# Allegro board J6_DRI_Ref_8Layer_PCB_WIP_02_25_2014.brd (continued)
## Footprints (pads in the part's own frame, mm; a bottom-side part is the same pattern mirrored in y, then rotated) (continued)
PBS32-12X57
  rect 0.305x1.448 smd: 1(-1.75,-3.277) 2(-1.25,-3.277) 3(-0.749,-3.277) 4(-0.249,-3.277) 5(0.249,-3.277) 6(0.749,-3.277) 7(1.25,-3.277) 8(1.75,-3.277) 17(1.75,3.277) 18(1.25,3.277) 19(0.749,3.277) 20(0.249,3.277) 21(-0.249,3.277) 22(-0.749,3.277) 23(-1.25,3.277) 24(-1.75,3.277)
  rect 1.448x0.305 smd: 9(3.277,-1.75) 10(3.277,-1.25) 11(3.277,-0.749) 12(3.277,-0.249) 13(3.277,0.249) 14(3.277,0.749) 15(3.277,1.25) 16(3.277,1.75) 25(-3.277,1.75) 26(-3.277,1.25) 27(-3.277,0.749) 28(-3.277,0.249) 29(-3.277,-0.249) 30(-3.277,-0.749) 31(-3.277,-1.25) 32(-3.277,-1.75)
POWERMITE-CASE457-04
  rect 2.667x2.54 smd: 1(0,0)
  rect 0.762x1.27 smd: 2(2.349,0)
PW20-14X70
  oval 0.356x1.778 smd: 1(-2.926,-2.987) 2(-2.276,-2.987) 3(-1.626,-2.987) 4(-0.975,-2.987) 5(-0.325,-2.987) 6(0.325,-2.987) 7(0.975,-2.987) 8(1.626,-2.987) 9(2.276,-2.987) 10(2.926,-2.987) 11(2.926,2.987) 12(2.276,2.987) 13(1.626,2.987) 14(0.975,2.987) 15(0.325,2.987) 16(-0.325,2.987) 17(-0.975,2.987) 18(-1.626,2.987) 19(-2.276,2.987) 20(-2.926,2.987)
PWR-Q5A-SLPS319
  rect 0.711x1.397 smd: 1(-1.905,0) 2(-0.635,0) 3(0.635,0) 4(1.905,0)
  custom 1.111x1.111 smd: 5(0,2.781)
QFN48-11X35
  rect 0.279x0.864 smd: 1(-2.748,-3.454) 2(-2.25,-3.454) 3(-1.75,-3.454) 4(-1.25,-3.454) 5(-0.749,-3.454) 6(-0.249,-3.454) 7(0.249,-3.454) 8(0.749,-3.454) 9(1.25,-3.454) 10(1.75,-3.454) 11(2.25,-3.454) 12(2.748,-3.454) 25(2.748,3.454) 26(2.25,3.454) 27(1.75,3.454) 28(1.25,3.454) 29(0.749,3.454) 30(0.249,3.454) 31(-0.249,3.454) 32(-0.749,3.454) 33(-1.25,3.454) 34(-1.75,3.454) 35(-2.25,3.454) 36(-2.748,3.454)
  rect 0.864x0.279 smd: 13(3.454,-2.748) 14(3.454,-2.25) 15(3.454,-1.75) 16(3.454,-1.25) 17(3.454,-0.749) 18(3.454,-0.249) 19(3.454,0.249) 20(3.454,0.749) 21(3.454,1.25) 22(3.454,1.75) 23(3.454,2.25) 24(3.454,2.748) 37(-3.454,2.748) 38(-3.454,2.25) 39(-3.454,1.75) 40(-3.454,1.25) 41(-3.454,0.749) 42(-3.454,0.249) 43(-3.454,-0.249) 44(-3.454,-0.749) 45(-3.454,-1.25) 46(-3.454,-1.75) 47(-3.454,-2.25) 48(-3.454,-2.748)
  rect 5.334x5.334 smd: 49(0,0)
QSE_020
  round 0.508 hole 1.041 unplated: (-10.058,-2.667) (10.058,-2.667)
  rect 0.406x2.286 smd: 1(7.569,2.87) 2(7.569,-2.87) 3(6.782,2.87) 4(6.782,-2.87) 5(5.969,2.87) 6(5.969,-2.87) 7(5.182,2.87) 8(5.182,-2.87) 9(4.369,2.87) 10(4.369,-2.87) 11(3.581,2.87) 12(3.581,-2.87) 13(2.769,2.87) 14(2.769,-2.87) 15(1.981,2.87) 16(1.981,-2.87) 17(1.168,2.87) 18(1.168,-2.87) 19(0.381,2.87) 20(0.381,-2.87) 21(-0.406,2.87) 22(-0.406,-2.87) 23(-1.219,2.87) 24(-1.219,-2.87) 25(-2.007,2.87) 26(-2.007,-2.87) 27(-2.819,2.87) 28(-2.819,-2.87) 29(-3.607,2.87) 30(-3.607,-2.87) 31(-4.42,2.87) 32(-4.42,-2.87) 33(-5.207,2.87) 34(-5.207,-2.87) 35(-6.02,2.87) 36(-6.02,-2.87) 37(-6.807,2.87) 38(-6.807,-2.87) 39(-7.595,2.87) 40(-7.595,-2.87)
  rect 2.794x0.432 smd: 41(-8.052,0) 44(8.052,0)
  rect 4.699x0.432 smd: 42(-3.175,0) 43(3.175,0)
QSH-030-01-F
  round 0.508 hole 1.016 unplated: (-10.061,2.667) (10.061,2.667)
  rect 0.279x2.273 smd: 1(-7.249,-2.865) 2(-7.249,2.865) 3(-6.749,-2.865) 4(-6.749,2.865) 5(-6.248,-2.865) 6(-6.248,2.865) 7(-5.748,-2.865) 8(-5.748,2.865) 9(-5.248,-2.865) 10(-5.248,2.865) 11(-4.75,-2.865) 12(-4.75,2.865) 13(-4.249,-2.865) 14(-4.249,2.865) 15(-3.749,-2.865) 16(-3.749,2.865) 17(-3.249,-2.865) 18(-3.249,2.865) 19(-2.748,-2.865) 20(-2.748,2.865) 21(-2.25,-2.865) 22(-2.25,2.865) 23(-1.75,-2.865) 24(-1.75,2.865) 25(-1.25,-2.865) 26(-1.25,2.865) 27(-0.749,-2.865) 28(-0.749,2.865) 29(-0.249,-2.865) 30(-0.249,2.865) 31(0.249,-2.865) 32(0.249,2.865) 33(0.749,-2.865) 34(0.749,2.865) 35(1.25,-2.865) 36(1.25,2.865) 37(1.75,-2.865) 38(1.75,2.865) 39(2.25,-2.865) 40(2.25,2.865) 41(2.748,-2.865) 42(2.748,2.865) 43(3.249,-2.865) 44(3.249,2.865) 45(3.749,-2.865) 46(3.749,2.865) 47(4.249,-2.865) 48(4.249,2.865) 49(4.75,-2.865) 50(4.75,2.865) 51(5.248,-2.865) 52(5.248,2.865) 53(5.748,-2.865) 54(5.748,2.865) 55(6.248,-2.865) 56(6.248,2.865) 57(6.749,-2.865) 58(6.749,2.865) 59(7.249,-2.865) 60(7.249,2.865)
  rect 2.54x0.432 smd: 61(-8.065,0) 64(8.065,0)
  rect 4.699x0.432 smd: 62(-3.175,0) 63(3.175,0)
R201-6P6SPC
  rect 0.47x0.381 smd: 1(-0.343,0) 2(0.343,0)
R402-25
  round 0.635 smd: 1(-0.508,0) 2(0.508,0)
R603-35X45
  oval 0.889x1.143 smd: 1(-0.762,0) 2(0.762,0)
R1206-40X70
  oval 1.016x1.778 smd: 1(-1.524,0) 2(1.524,0)
R2512
  rect 1.651x3.175 smd: 1(-3.239,0) 2(3.239,0)
R2725-125X250
  rect 3.175x6.858 smd: 1(-2.248,0) 2(2.248,0)
RGY16-12X34
  oval 0.864x0.305 smd: 1(-2.032,-0.749) 8(2.032,-0.749) 9(2.032,0.749) 16(-2.032,0.749)
  oval 0.305x0.864 smd: 2(-1.252,-1.765) 3(-0.752,-1.765) 4(-0.252,-1.765) 5(0.249,-1.765) 6(0.749,-1.765) 7(1.25,-1.765) 10(1.25,1.765) 11(0.749,1.765) 12(0.249,1.765) 13(-0.252,1.765) 14(-0.752,1.765) 15(-1.252,1.765)
  rect 2.489x2.032 smd: 17(0,0)
RGZ48-11X34
  rect 0.279x0.864 smd: 1(-2.748,-3.531) 2(-2.25,-3.531) 3(-1.75,-3.531) 4(-1.25,-3.531) 5(-0.749,-3.531) 6(-0.249,-3.531) 7(0.249,-3.531) 8(0.749,-3.531) 9(1.25,-3.531) 10(1.75,-3.531) 11(2.25,-3.531) 12(2.748,-3.531) 25(2.748,3.531) 26(2.25,3.531) 27(1.75,3.531) 28(1.25,3.531) 29(0.749,3.531) 30(0.249,3.531) 31(-0.249,3.531) 32(-0.749,3.531) 33(-1.25,3.531) 34(-1.75,3.531) 35(-2.25,3.531) 36(-2.748,3.531)
  rect 0.864x0.279 smd: 13(3.531,-2.748) 14(3.531,-2.25) 15(3.531,-1.75) 16(3.531,-1.25) 17(3.531,-0.749) 18(3.531,-0.249) 19(3.531,0.249) 20(3.531,0.749) 21(3.531,1.25) 22(3.531,1.75) 23(3.531,2.25) 24(3.531,2.748) 37(-3.531,2.748) 38(-3.531,2.25) 39(-3.531,1.75) 40(-3.531,1.25) 41(-3.531,0.749) 42(-3.531,0.249) 43(-3.531,-0.249) 44(-3.531,-0.749) 45(-3.531,-1.25) 46(-3.531,-1.75) 47(-3.531,-2.25) 48(-3.531,-2.748)
  rect 5.334x5.334 smd: 49(0,0)
RHL24-PVQFN-TI
  rect 0.711x0.305 smd: 1(-2.819,-0.953) 12(2.819,-0.953) 13(2.819,0.953) 24(-2.819,0.953)
  rect 0.305x0.711 smd: 2(-2.25,-1.829) 3(-1.75,-1.829) 4(-1.25,-1.829) 5(-0.749,-1.829) 6(-0.249,-1.829) 7(0.249,-1.829) 8(0.749,-1.829) 9(1.25,-1.829) 10(1.75,-1.829) 11(2.25,-1.829) 14(2.25,1.829) 15(1.75,1.829) 16(1.25,1.829) 17(0.749,1.829) 18(0.249,1.829) 19(-0.249,1.829) 20(-0.749,1.829) 21(-1.25,1.829) 22(-1.75,1.829) 23(-2.25,1.829)
  custom 0.508x0.508 smd: 25(0,0)
RPAK8-10X25-28V
  rect 0.406x0.635 smd: 1(-0.823,-0.521) 4(0.823,-0.521) 5(0.823,0.521) 8(-0.823,0.521)
  rect 0.254x0.635 smd: 2(-0.249,-0.521) 3(0.249,-0.521) 6(0.249,0.521) 7(-0.249,0.521)
RTE16-12X34
  oval 0.305x0.864 smd: 1(-0.747,-1.524) 2(-0.249,-1.524) 3(0.249,-1.524) 4(0.747,-1.524) 9(0.747,1.524) 10(0.249,1.524) 11(-0.249,1.524) 12(-0.747,1.524)
  oval 0.864x0.305 smd: 5(1.524,-0.747) 6(1.524,-0.249) 7(1.524,0.249) 8(1.524,0.747) 13(-1.524,0.747) 14(-1.524,0.249) 15(-1.524,-0.249) 16(-1.524,-0.747)
  rect 1.524x1.524 smd: 17(0,0)
SD12-202X60
  custom 0.559x0.559 smd: 1(-2.972,0) 2(2.972,0)
SO8-25X75
  oval 0.635x1.905 smd: 1(-1.905,-2.794) 2(-0.635,-2.794) 3(0.635,-2.794) 4(1.905,-2.794) 5(1.905,2.794) 6(0.635,2.794) 7(-0.635,2.794) 8(-1.905,2.794)
SO8-25X75-295
  oval 0.635x2.54 smd: 1(-1.905,-3.086) 2(-0.635,-3.086) 3(0.635,-3.086) 4(1.905,-3.086) 5(1.905,3.086) 6(0.635,3.086) 7(-0.635,3.086) 8(-1.905,3.086)
SO16-25X75-300
  oval 0.635x1.905 smd: 1(-4.445,-4.699) 2(-3.175,-4.699) 3(-1.905,-4.699) 4(-0.635,-4.699) 5(0.635,-4.699) 6(1.905,-4.699) 7(3.175,-4.699) 8(4.445,-4.699) 9(4.445,4.699) 10(3.175,4.699) 11(1.905,4.699) 12(0.635,4.699) 13(-0.635,4.699) 14(-1.905,4.699) 15(-3.175,4.699) 16(-4.445,4.699)
ST_3500
  round 0.508 hole 1.6 unplated: (0,3.797) (0,-3.188)
  rect 2.54x2.388 smd: 1(-3.683,4.915) 2(-3.48,-4.407) 3(3.683,3.01)
  rect 2.921x2.489 smd: 4(0.762,-8.42)
SW4-7914G
  rect 1.27x1.778 smd: 1(1.27,2.769) 2(1.27,-2.769) 3(-1.27,2.769) 4(-1.27,-2.769)
TO-252-D-PAK
  rect 1.397x3.048 smd: 1(-2.311,-6.413) 3(2.311,-6.413)
  rect 6.35x7.62 smd: 4(0,0.102)
TP1-18RD8
  round 0.457 hole 0.203: 1(0,0)
TP20
  round 0.762 smd: 1(0,0)
unnamed
  round 1.27 smd: 1(0,0)
XTAL2-75X94
  rect 1.905x2.413 smd: 1(-2.235,0) 2(2.235,0)
XTAL2-CM519-DUAL-CTS407
  rect 1.295x2.21 smd: 1(-2.1,0) 2(2.1,0)
  rect 1.397x2.21 smd: 3(-1.27,3.2) 4(-1.27,-3.2) 5(1.27,-3.2) 6(1.27,3.2)
XTAL4-23X47-SSP-T7
  rect 1.194x0.584 smd: 1(-3.15,-0.445) 2(3.15,-0.445) 3(3.15,0.445) 4(-3.15,0.445)
XTAL4-55X87
  rect 2.21x1.397 smd: 1(-2.896,-1.25) 2(2.896,-1.25) 3(2.896,1.25) 4(-2.896,1.25)
ZWS169-13P8
  round 0.35 smd: A1(4.8,-4.8) A2(4,-4.8) A3(3.2,-4.8) A4(2.4,-4.8) A5(1.6,-4.8) A6(0.8,-4.8) A7(0,-4.8) A8(-0.8,-4.8) A9(-1.6,-4.8) A10(-2.4,-4.8) A11(-3.2,-4.8) A12(-4,-4.8) A13(-4.8,-4.8) B1(4.8,-4) B2(4,-4) B3(3.2,-4) B4(2.4,-4) B5(1.6,-4) B6(0.8,-4) B7(0,-4) B8(-0.8,-4) B9(-1.6,-4) B10(-2.4,-4) B11(-3.2,-4) B12(-4,-4) B13(-4.8,-4) C1(4.8,-3.2) C2(4,-3.2) C3(3.2,-3.2) C4(2.4,-3.2) C5(1.6,-3.2) C6(0.8,-3.2) C7(0,-3.2) C8(-0.8,-3.2) C9(-1.6,-3.2) C10(-2.4,-3.2) C11(-3.2,-3.2) C12(-4,-3.2) C13(-4.8,-3.2) D1(4.8,-2.4) D2(4,-2.4) D3(3.2,-2.4) D4(2.4,-2.4) D5(1.6,-2.4) D6(0.8,-2.4) D7(0,-2.4) D8(-0.8,-2.4) D9(-1.6,-2.4) D10(-2.4,-2.4) D11(-3.2,-2.4) D12(-4,-2.4) D13(-4.8,-2.4) E1(4.8,-1.6) E2(4,-1.6) E3(3.2,-1.6) E4(2.4,-1.6) E5(1.6,-1.6) E6(0.8,-1.6) E7(0,-1.6) E8(-0.8,-1.6) E9(-1.6,-1.6) E10(-2.4,-1.6) E11(-3.2,-1.6) E12(-4,-1.6) E13(-4.8,-1.6) F1(4.8,-0.8) F2(4,-0.8) F3(3.2,-0.8) F4(2.4,-0.8) F5(1.6,-0.8) F6(0.8,-0.8) F7(0,-0.8) F8(-0.8,-0.8) F9(-1.6,-0.8) F10(-2.4,-0.8) F11(-3.2,-0.8) F12(-4,-0.8) F13(-4.8,-0.8) G1(4.8,0) G2(4,0) G3(3.2,0) G4(2.4,0) G5(1.6,0) G6(0.8,0) G7(0,0) G8(-0.8,0) G9(-1.6,0) G10(-2.4,0) G11(-3.2,0) G12(-4,0) G13(-4.8,0) H1(4.8,0.8) H2(4,0.8) H3(3.2,0.8) H4(2.4,0.8) H5(1.6,0.8) H6(0.8,0.8) H7(0,0.8) H8(-0.8,0.8) H9(-1.6,0.8) H10(-2.4,0.8) H11(-3.2,0.8) H12(-4,0.8) H13(-4.8,0.8) J1(4.8,1.6) J2(4,1.6) J3(3.2,1.6) J4(2.4,1.6) J5(1.6,1.6) J6(0.8,1.6) J7(0,1.6) J8(-0.8,1.6) J9(-1.6,1.6) J10(-2.4,1.6) J11(-3.2,1.6) J12(-4,1.6) J13(-4.8,1.6) K1(4.8,2.4) K2(4,2.4) K3(3.2,2.4) K4(2.4,2.4) K5(1.6,2.4) K6(0.8,2.4) K7(0,2.4) K8(-0.8,2.4) K9(-1.6,2.4) K10(-2.4,2.4) K11(-3.2,2.4) K12(-4,2.4) K13(-4.8,2.4) L1(4.8,3.2) L2(4,3.2) L3(3.2,3.2) L4(2.4,3.2) L5(1.6,3.2) L6(0.8,3.2) L7(0,3.2) L8(-0.8,3.2) L9(-1.6,3.2) L10(-2.4,3.2) L11(-3.2,3.2) L12(-4,3.2) L13(-4.8,3.2) M1(4.8,4) M2(4,4) M3(3.2,4) M4(2.4,4) M5(1.6,4) M6(0.8,4) M7(0,4) M8(-0.8,4) M9(-1.6,4) M10(-2.4,4) M11(-3.2,4) M12(-4,4) M13(-4.8,4) N1(4.8,4.8) N2(4,4.8) N3(3.2,4.8) N4(2.4,4.8) N5(1.6,4.8) N6(0.8,4.8) N7(0,4.8) N8(-0.8,4.8) N9(-1.6,4.8) N10(-2.4,4.8) N11(-3.2,4.8) N12(-4,4.8) N13(-4.8,4.8)

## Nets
1V8_I2C1_SCL: P9.31 R597.2 R708.1 U45.L1(I2C1_SCL_SCK) U50.3(SCL1)
1V8_I2C1_SDA: P9.33 R593.2 R709.1 U45.L2(I2C1_SDA_SDI) U50.4(SDA1)
GND: C7.2 C8.2 C13.2 C14.2 C15.2 C16.2 C45.2 C47.2 C49.2 C50.2 C51.2 C52.2 C60.1 C61.1 C62.1 C63.1 C67.2 C71.2 C72.2 C74.2 C76.1 C77.2 C78.1 C79.2 C80.2 C86.2 C87.2 C89.2 C90.1 C91.1 C92.1 C93.1 C94.1 C95.1 C96.1 C99.1 C100.1 C101.2 C102.1 C103.1 C104.2 C105.1 C106.2 C107.2 C108.1 C109.2 C110.2 C111.1 C112.2 C113.2 C115.2 C116.2 C117.2 C118.2 C119.2 C130.2 C131.2 C132.2 C133.2 C134.2 C136.2 C137.2 C138.2 C139.2 C140.2 C141.2 C142.2 C143.2 C144.2 C147.2 C148.2 C151.2 C152.2 C153.2 C154.2 C155.2 C156.2 C157.1 C158.2 C159.2 C160.2 C161.2 C162.2 C163.2 C169.2 C170.2 C171.2 C172.2 C174.1 C177.2 C178.2 C179.1 C182.2 C183.2 C184.2 C185.2 C186.1 C187.1 C188.1 C189.2 C190.2 C191.1 C192.1 C193.2 C194.2 C195.2 C196.2 C199.2 C200.2 C201.1 C202.1 C210.2 C211.2 C212.2 C213.2 C214.2 C228.2 C229.2 C231.2 C232.2 C233.2 C234.2 C235.2 C236.2 C269.2 C273.2 C274.2 C280.2 C290.2 C293.2 C295.1 C304.1 C305.2 C306.2 C309.1 C314.2 C318.2 C319.2 C325.2 C326.1 C327.1 C328.1 C329.2 C330.2 C331.2 C332.2 C335.2 C338.1 C340.2 C341.1 C342.1 C344.2 C345.2 C346.1 C348.2 C349.1 C350.1 C351.2 C352.2 C353.1 C354.1 C355.2 C356.2 C357.2 C358.2 C359.1 C360.1 C363.1 C364.1 C365.2 C366.2 C367.1 C368.1 C369.2 C370.1 C371.2 C372.2 C373.1 C374.1 C375.1 C376.1 C377.1 C378.1 C379.1 C380.1 C381.1 C382.2 C384.2 C385.2 C386.1 C387.2 C388.1 C389.2 C390.1 C391.1 C392.1 C393.1 C394.1 C395.1 C396.2 C399.1 C400.1 C401.2 C402.2 C403.1 C404.2 C405.2 C406.2 C407.1 C408.1 C409.1 C410.1 C411.2 C412.1 C413.2 C414.1 C415.1 C416.2 C417.2 C418.2 C419.2 C420.2 C421.2 C422.2 C423.2 C424.2 C425.2 C426.2 C427.2 C429.2 C430.2 C431.2 C432.1 C433.2 C434.1 C435.2 C436.2 C437.1 C438.2 C439.2 C440.2 C441.2 C442.2 C443.2 C444.1 C445.2 C446.2 C447.2 C448.2 C449.2 C450.1 C451.2 C453.1 C454.2 C455.1 C456.1 C457.2 C458.1 C459.1 C460.2 C461.1 C462.2 C463.2 C464.2 C465.1 C466.2 C467.2 C468.2 C469.2 C470.2 C471.2 C472.2 C473.2 C474.2 C475.2 C477.2 C478.1 C479.2 C480.2 C481.2 C482.2 C483.1 C484.2 C485.2 C486.2 C487.1 C489.2 C490.2 C491.2 C492.2 C493.2 C494.2 C495.2 C496.2 C497.2 C498.1 C500.2 C501.2 C502.2 C503.2 C504.2 C506.2 C507.1 C508.2 C509.2 C510.2 C511.2 C512.2 C513.1 C514.2 C516.2 C517.2 C518.1 C519.2 C520.2 C521.2 C522.2 C523.1 C524.2 C525.2 C526.2 C527.2 C528.2 C529.2 C530.2 C531.2 C532.2 C535.2 C536.2 C537.2 C538.2 C539.2 C540.2 C541.2 C542.1 C545.2 C546.2 C548.2 C549.2 C550.2 C553.2 C556.2 C557.2 C559.2 C560.2 C561.2 C562.2 C563.2 C564.2 C565.2 C566.2 C567.2 C568.2 C569.2 C570.2 C571.2 C572.2 C573.2 C574.2 C575.2 C576.2 C577.2 C578.2 C579.1 C580.2 C581.2 C582.2 C583.2 C584.2 C585.2 C586.2 C587.2 C588.2 C589.2 C590.2 C591.2 C592.2 C593.2 C594.2 C595.2 C596.2 C597.2 C598.2 C600.2 C602.2 C603.2 C605.2 C606.2 C607.1 C608.2 C609.2 C610.2 C611.2 C612.2 C613.2 C614.2 C615.2 C616.2 C617.2 C618.2 C619.2 C621.2 C622.2 C623.2 C624.2 C625.2 C628.2 C629.2 C630.2 C631.2 C632.2 C633.2 C636.2 C637.2 C638.2 C639.2 C640.2 C641.2 C644.2 C645.2 C649.2 C650.2 C655.2 C656.2 C657.2 C658.1 C659.1 C664.2 C665.2 C666.2 C667.2 C668.2 C669.2 C670.2 C671.2 C672.2 C673.2 C674.2 C675.2 C676.2 C677.2 C678.2 C679.2 C680.2 C683.2 C693.2 C696.2 C708.2 C715.2 C716.2 C717.2 C718.2 C719.2 C720.2 C721.2 C733.1 C734.1 C735.2 C785.2 C786.2 C787.2 C789.1 C790.1 C792.2 C793.2 C794.2 C795.2 C796.2 C797.1 C798.2 C799.2 C800.1 C801.1 C810.1 E1.2 E2.2 E3.2 E4.2 E5.2 E6.2 E8.2 E9.2 E10.2 E11.2 J17.16(GND16) J17.57(GND57) J17.58(GND58) J17.61(GNDCT1) J17.62(GNDCT2) J17.63(GNDCT3) J17.64(GNDCT4) P1.17 P1.18 P1.41(G1) P1.42(G2) P1.43(G3) P1.44(G4) P5.9 P5.10 P9.2 P9.3 P9.6 P9.9 P9.18 P9.19 P9.22 P9.37 P9.42 P9.47 P9.60 P9.63 P9.64 P9.77 P9.83 P9.87 P9.92 P9.95 P9.97 P12.1(SHIELD) P14.6(VSS) Q3.1(S1) Q3.2(S2) Q3.3(S3) Q4.1(S1) Q4.2(S2) Q4.3(S3) R9.2 R10.2 R11.2 R83.1 R84.1 R85.1 R110.2 R111.2 R112.2 R116.2 R117.2 R118.2 R119.2 R120.2 R121.2 R122.2 R123.2 R124.2 R125.2 R145.1 R152.2 R154.2 R157.2 R178.2 R179.2 R191.2 R196.2 R200.2 R205.2 R206.2 R241.2 R245.2 R256.1 R257.2 R260.2 R262.2 R266.2 R273.1 R276.1 R277.1 R278.1 R287.2 R288.2 R289.2 R291.1 R333.2 R338.2 R455.1 R461.1 R463.1 R464.1 R472.1 R473.2 R481.1 R483.2 R513.2 R515.2 R518.2 R529.2 R532.1 R535.2 R537.2 R555.1 R565.2 R569.1 R570.2 R574.2 R576.2 R578.2 R588.2 R589.2 R590.2 R591.2 R592.2 R599.1 R615.2 R617.2 R620.2 R625.2 R636.2 R642.2 R643.2 R644.2 R675.2 R691.2 R692.2 R693.2 R694.2 R695.2 R702.2 R714.1 R715.2 R760.1 R762.1 R832.2 R838.2 R848.2 R849.2 R911.2 R915.2 R943.1 R946.1 R953.1 R954.1 R955.2 R958.2 R?.2 SW4.1(A) SW4.2(AA) U3.15(RES0) U3.18(RES1(RES2)) U3.49(DAP(PWRPAD)) U6.3(GND) U8.4(TAB) U18.10(VSS) U23.9(PGNDA) U23.19(AGND.1) U23.23(AGND.2) U23.30(PGNDB) U23.39(PWR PAD) U35.2(DIR) U35.11(GND#11) U35.12(GND#12) U35.13(GND#13) U35.25(PP) U36.1(GND) U37.2(GND) U41.7(2A2) U41.8(GND.1) U41.9(GND.2) U41.17(GND.3) U43.1(GND) U44.2(GND) U45.A1(SUB_GND_A1) U45.A4(REFGND1) U45.A7(GNDANA) U45.A13(SUB_GND_A13) U45.B2(GPADC_IN0) U45.B10(SUB_GND_B10) U45.B11(SUB_GND_B11) U45.C2(GPADC_IN1) U45.C3(GPADC_IN2) U45.C12(SMPS12_FBK_GND) U45.D4(SMPS7_GND_1) U45.D5(SMPS7_GND_2) U45.D6(SUB_GND_D6) U45.D7(SUB_GND_D7) U45.D10(SMPS1_GND_1) U45.E4(SMPS7_GND_3) U45.E7(VAC/ACOK) U45.E8(SUB_GND_E8) U45.E9(SMPS1_GND_2) U45.E10(SMPS1_GND_3) U45.F4(SMPS4_GND_1) U45.F5(AGND.1) U45.F6(SUB_GND_F6) U45.F7(SUB_GND_F7) U45.F9(SMPS2_GND_1) U45.F10(SMPS2_GND_2) U45.G4(SMPS4_GND_2) U45.G5(SMPS4_GND_3) U45.G7(SUB_GND_G7) U45.G10(SMPS2_GND_3) U45.H4(SMPS5_GND_1) U45.H5(SMPS5_GND_2) U45.H6(SUB_GND_H6) U45.H7(SUB_GND_H7) U45.H10(SMPS3_GND_1) U45.J4(SMPS5_GND_3) U45.J6(SUB_GND_J6) U45.J9(SMPS3_GND_2) U45.J10(SMPS3_GND_3) U45.K3(SMPS45_FDBK_GND) U45.L5(SMPS6_GND) U45.L6(SMPS6_GND_1) U45.L7(SMPS9_GND) U45.L8(SMPS9_GND_1) U45.L9(SMPS8_GND_1) U45.L10(SMPS8_GND) U45.M1(SUB_GND_M1) U45.M2(SUB_GND_M2) U45.M12(GND_DIG) U45.M13(AGND.2) U45.N1(SUB_GND_N1) U45.N2(VIO_GND) U45.N13(SUB_GND_N13) U46.11(GND#11) U46.12(GND#12) U46.13(GND#13) U46.25(PP) U48.7(2A2) U48.8(GND.1) U48.9(GND.2) U48.17(GND.3) U50.1(GND) U52.A1(VSS.9) U52.A2(VSS.11) U52.A6(VSS.15) U52.A14(VSS.41) U52.A23(VSS.68) U52.A28(VSS.79) U52.AA8(VSS.17) U52.AA9(VSS.19) U52.AA10(VSS.14) U52.AA11(VSSA_USB.2) U52.AA14(VSS.48) U52.AA15(VSS.51) U52.AA20(VSS.61) U52.AB11(VSSA_USB.1) U52.AB14(VSS.40) U52.AB20(VSS.60) U52.AD1(VSS.3) U52.AD10(VSSA_USB3) U52.AD13(VSSA_PCIE.1) U52.AD19(VSSA_HDMI.2) U52.AD24(VSS.70) U52.AE10(VSSA_SATA) U52.AE13(VSSA_PCIE.2) U52.AE19(VSSA_HDMI.1) U52.AG1(VSS.2) U52.AH1(VSS.1) U52.AH2(VSS.10) U52.AH8(VSS.53) U52.AH20(VSS.52) U52.AH28(VSS.75) U52.B1(VSS.8) U52.D13(VSS.39) U52.D19(VSS.59) U52.E13(VSS.38) U52.E19(VSS.58) U52.F1(VSS.7) U52.F7(VSS.54) U52.G7(VSS.57) U52.G8(VSS.65) U52.G9(VSS.66) U52.H12(VSS.33) U52.J12(VSS.32) U52.J15(VSS.XX) U52.J28(VSS.78) U52.K1(VSS.6) U52.K4(VSS.12) U52.K5(VSS.13) U52.K15(VSS.28) U52.K24(VSS.55) U52.K25(VSS.56) U52.L13(VSS.37) U52.L14(VSS.46) U52.M19(VSS.69) U52.N14(VSS.X5) U52.N15(VSS.16) U52.N19(VSS.18) U52.N24(VSS.72) U52.N25(VSS.74) U52.P28(VSS.77) U52.R1(VSS.5) U52.R12(VSS.29) U52.R13(VSS.X6) U52.R15(VSS.43) U52.R21(VSS.64) U52.T10(VSS.21) U52.T11(VSS.26) U52.T12(VSS.23) U52.T14(VSS.X7) U52.T15(VSS.42) U52.T17(VSS.47) U52.T18(VSS.24) U52.T21(VSS.27) U52.U14(VSSA_VIDEO) U52.U15(VSS.X8) U52.U17(VSS.X9) U52.U20(VSS.62) U52.U21(VSS.63) U52.V15(VSS.30) U52.V17(VSS.X10) U52.W1(VSS.4) U52.W15(VSS.36) U52.W24(VSS.71) U52.W25(VSS.73) U52.W28(VSS.76) U54.2(GND) U55.2(GND) U55.3(ENN) U56.6(GND) U56.11(PP1) U59.15(AVSS_ADC) U59.20(DRVSS.1) U59.21(DRVSS.2) U59.26(AVSS_DAC) U59.42(DVSS) U59.49(TPAD) U62.3(GND) U63.3(GND.1) U63.4(GND.2) U63.5(AGND) U63.17(PWRPAD) U64.4(PGND) U64.8(GND) U64.11(PWRPAD) U65.A9(VSS.1) U65.B1(VSSQ.1) U65.B3(VSS.2) U65.B9(VSSQ.2) U65.D1(VSSQ.3) U65.D8(VSSQ.4) U65.E1(VSS.3) U65.E2(VSSQ.5) U65.E8(VSSQ.6) U65.F9(VSSQ.7) U65.G1(VSSQ.8) U65.G8(VSS.4) U65.G9(VSSQ.9) U65.J2(VSSDL) U65.J8(VSS.5) U65.M1(VSS.6) U65.M9(VSS.7) U65.P1(VSS.8) U65.P9(VSS.9) U65.T1(VSS.10) U65.T9(VSS.11) U66.A9(VSS.1) U66.B1(VSSQ.1) U66.B3(VSS.2) U66.B9(VSSQ.2) U66.D1(VSSQ.3) U66.D8(VSSQ.4) U66.E1(VSS.3) U66.E2(VSSQ.5) U66.E8(VSSQ.6) U66.F9(VSSQ.7) U66.G1(VSSQ.8) U66.G8(VSS.4) U66.G9(VSSQ.9) U66.J2(VSSDL) U66.J8(VSS.5) U66.M1(VSS.6) U66.M9(VSS.7) U66.P1(VSS.8) U66.P9(VSS.9) U66.T1(VSS.10) U66.T9(VSS.11) U67.A1(VSS.1) U67.A8(VSS.2) U67.B1(VSS.3) U67.B2(VSSQ#B2) U67.B8(VSSQ#B8) U67.C9(VSSQ#C9) U67.D1(VSSQ#D1) U67.D8(VSS.4) U67.D9(VSSQ#D9) U67.F2(VSS.5) U67.F8(VSS.6) U67.J1(VSS.7) U67.J9(VSS.8) U67.L1(VSS.9) U67.L9(VSS.10) U67.N1(VSS.11) U67.N9(VSS.12) U68.A1(VSS.1) U68.A8(VSS.2) U68.B1(VSS.3) U68.B2(VSSQ#B2) U68.B8(VSSQ#B8) U68.C9(VSSQ#C9) U68.D1(VSSQ#D1) U68.D8(VSS.4) U68.D9(VSSQ#D9) U68.F2(VSS.5) U68.F8(VSS.6) U68.J1(VSS.7) U68.J9(VSS.8) U68.L1(VSS.9) U68.L9(VSS.10) U68.N1(VSS.11) U68.N9(VSS.12) U69.A1(VSS.1) U69.A8(VSS.2) U69.B1(VSS.3) U69.B2(VSSQ#B2) U69.B8(VSSQ#B8) U69.C9(VSSQ#C9) U69.D1(VSSQ#D1) U69.D8(VSS.4) U69.D9(VSSQ#D9) U69.F2(VSS.5) U69.F8(VSS.6) U69.J1(VSS.7) U69.J9(VSS.8) U69.L1(VSS.9) U69.L9(VSS.10) U69.N1(VSS.11) U69.N9(VSS.12) U72.8(GND) U72.11(PWR_PAD) U73.8(GND) U73.11(PWR_PAD) U77.4(GND) U78.4(GND) U79.4(GND) U92.5(GND) U92.9(PWR_PAD) U100.11(GND1) U100.17(B3) U100.18(B2) U100.20(B1) U101.4(GND) U101.5(DIR) U102.2(GND) U104.2(GND) U104.5(DIR) U105.4(VSS) U110.3(GND) U115.A1(VSS.1) U115.A8(VSS.2) U115.B1(VSS.3) U115.B2(VSSQ#B2) U115.B8(VSSQ#B8) U115.C9(VSSQ#C9) U115.D1(VSSQ#D1) U115.D8(VSS.4) U115.D9(VSSQ#D9) U115.F2(VSS.5) U115.F8(VSS.6) U115.J1(VSS.7) U115.J9(VSS.8) U115.L1(VSS.9) U115.L9(VSS.10) U115.N1(VSS.11) U115.N9(VSS.12) U116.A1(VSS.1) U116.A8(VSS.2) U116.B1(VSS.3) U116.B2(VSSQ#B2) U116.B8(VSSQ#B8) U116.C9(VSSQ#C9) U116.D1(VSSQ#D1) U116.D8(VSS.4) U116.D9(VSSQ#D9) U116.F2(VSS.5) U116.F8(VSS.6) U116.J1(VSS.7) U116.J9(VSS.8) U116.L1(VSS.9) U116.L9(VSS.10) U116.N1(VSS.11) U116.N9(VSS.12) U117.2(GND) U121.C4(VSS.1) U121.E7(VSS.2) U121.G5(VSS.3) U121.H10(VSS.4) U121.K8(VSS.5) U121.N2(VSS.6) U121.N7(VSS.7) U121.P4(VSS.8) U121.P6(VSS.9) U122.5(GND) U123.2(GND) U129.3(GND) U130.3(GND) U131.4(GND) U132.3(PLL_AGND) U132.7(AGND) U132.19(DGND) U132.31(CH_AGND) Y3.2 Y3.3
VBATT_12V: F1.2 R453.2
VBUS_USB1: C80.1 L8.1 U73.9(VBUS.2) U73.10(VBUS.1)
VBUS_USB1_SW: C79.1 L8.2 R154.1 U36.6(OUT3) U36.7(OUT2) U36.8(OUT1)
VBUS_USB2: C87.1 L12.1 U72.9(VBUS.2) U72.10(VBUS.1)
VBUS_USB2_SW: C86.1 L12.2 R179.1 U43.6(OUT3) U43.7(OUT2) U43.8(OUT1)
VCC_SENSE: R549.2 U45.B3(VCC_SENSE)
VDD_???: U45.B1(SMPS7_FDBK) U45.L11(SMPS8_FDBK)
VDD_CORE: C326.2 C363.2 C364.2 C386.2 C388.2 C390.2 C393.2 C394.2 C395.2 C456.2 C487.2 C498.2 L11.1 U45.K6(SMPS6_FBK) U52.H13(VDD.18) U52.H14(VDD.22) U52.J17(VDD.X1) U52.J18(VDD.X2) U52.L7(VDD.34) U52.L8(VDD.15) U52.N10(VDD.6) U52.N13(VDD.16) U52.P11(VDD.9) U52.P12(VDD.12) U52.P13(VDD.X3) U52.R11(VDD.8) U52.R16(VDD.26) U52.R19(VDD.27) U52.T13(VDD.13) U52.T16(VDD.25) U52.T19(VDD.X7) U52.U8(VDD.29) U52.U9(VDD.2) U52.U13(VDD.3) U52.U16(VDD.X8) U52.V8(VDD.1) U52.V16(VDD.X9)
VDD_DCDC_DDR_1V35: C154.1 L20.2 R279.2
VDD_DDR: C136.1 C137.1 C138.1 C139.1 C140.1 C143.1 C148.1 C158.1 C159.1 C160.1 C161.1 C162.1 C163.1 C164.2 C165.2 C166.2 C167.2 C169.1 C170.1 C171.1 C172.1 C175.2 C176.2 C180.2 C181.2 C182.1 C183.1 C184.1 C185.1 C187.2 C189.1 C190.1 C191.2 C193.1 C194.1 C195.1 C196.1 C197.2 C198.2 C199.1 C200.1 C201.2 C203.2 C204.2 C205.2 C206.2 C207.2 C208.2 C209.2 C210.1 C211.1 C212.1 C213.1 C214.1 C350.2 C508.1 C528.1 C537.1 C541.1 C548.1 C549.1 C556.1 C557.1 C559.1 C560.1 C561.1 C562.1 C563.1 C564.1 C569.1 C570.1 C571.1 C572.1 C574.1 C576.1 C577.1 C578.1 C580.1 C581.1 C582.1 C583.1 C584.1 C585.1 C586.1 C587.1 C588.1 C589.1 C590.1 C591.1 C592.1 C593.1 C594.1 C595.1 C596.1 C597.1 C598.1 C599.2 C600.1 C601.2 C602.1 C603.1 C605.1 C606.1 C608.1 C609.1 C610.1 C611.1 C612.1 C613.1 C614.1 C615.1 C616.1 C621.1 C622.1 C623.1 C624.1 C625.1 C626.2 C627.2 C630.1 C631.1 C632.1 C633.1 C634.2 C635.2 C636.1 C637.1 C638.1 C639.1 C640.1 C641.1 C642.2 C643.2 C644.1 C645.1 C649.1 C650.1 C651.2 C652.2 C653.2 C654.2 C655.1 C656.1 C657.1 C659.2 C660.2 C661.2 C662.2 C663.2 C664.1 C665.1 C666.1 C667.1 C668.1 C669.1 C670.1 C671.1 C672.1 C673.1 C674.1 C675.1 C676.1 C677.1 C678.1 C679.1 L13.1 R292.2 U45.K13(SMPS3_FDBK) U52.AA21(VDDS_DDR1.4) U52.AA22(VDDS_DDR1.2) U52.AB21(VDDS_DDR1.3) U52.AB22(VDDS_DDR1.7) U52.AB24(VDDS_DDR1.10) U52.AB25(VDDS_DDR1.11) U52.AC22(VDDS_DDR1.6) U52.AD26(VDDS_DDR1.12) U52.AG20(VDDS_DDR1.9) U52.AG28(VDDS_DDR1.5) U52.AH27(VDDS_DDR1.13) U52.E24(VDDS_DDR2.9) U52.G22(VDDS_DDR2.5) U52.G23(VDDS_DDR2.6) U52.H20(VDDS_DDR2.1) U52.H21(VDDS_DDR2.11) U52.H22(VDDS_DDR2.4) U52.J27(VDDS_DDR2.12) U52.L20(VDDS_DDR2.8) U52.L21(VDDS_DDR2.3) U52.M20(VDDS_DDR2.13) U52.M21(VDDS_DDR2.2) U52.T24(VDDS_DDR2.7) U52.T25(VDDS_DDR2.10) U52.W16(VDDS_DDR1.1) U52.W27(VDDS_DDR1.8) U64.2(VLDOIN) U65.A1(VDDQ.1) U65.A8(VDDQ.2) U65.B2(VDD.1) U65.C1(VDDQ.3) U65.C9(VDDQ.4) U65.D2(VDDQ.5) U65.D9(VDD.2) U65.E9(VDDQ.6) U65.F1(VDDQ.7) U65.G7(VDD.3) U65.H2(VDDQ.8) U65.H9(VDDQ.9) U65.K2(VDDL) U65.K8(VDD.4) U65.N1(VDD.5) U65.N9(VDD.6) U65.R1(VDD.7) U65.R9(VDD.8) U66.A1(VDDQ.1) U66.A8(VDDQ.2) U66.B2(VDD.1) U66.C1(VDDQ.3) U66.C9(VDDQ.4) U66.D2(VDDQ.5) U66.D9(VDD.2) U66.E9(VDDQ.6) U66.F1(VDDQ.7) U66.G7(VDD.3) U66.H2(VDDQ.8) U66.H9(VDDQ.9) U66.K2(VDDL) U66.K8(VDD.4) U66.N1(VDD.5) U66.N9(VDD.6) U66.R1(VDD.7) U66.R9(VDD.8) U67.A2(VDD.1) U67.A9(VDD.2) U67.B9(VDDQ.1) U67.C1(VDDQ.2) U67.D7(VDD.3) U67.E2(VDDQ.3) U67.E9(VDDQ.4) U67.G2(VDD.4) U67.G8(VDD.5) U67.K1(VDD.6) U67.K9(VDD.7) U67.M1(VDD.8) U67.M9(VDD.9) U68.A2(VDD.1) U68.A9(VDD.2) U68.B9(VDDQ.1) U68.C1(VDDQ.2) U68.D7(VDD.3) U68.E2(VDDQ.3) U68.E9(VDDQ.4) U68.G2(VDD.4) U68.G8(VDD.5) U68.K1(VDD.6) U68.K9(VDD.7) U68.M1(VDD.8) U68.M9(VDD.9) U69.A2(VDD.1) U69.A9(VDD.2) U69.B9(VDDQ.1) U69.C1(VDDQ.2) U69.D7(VDD.3) U69.E2(VDDQ.3) U69.E9(VDDQ.4) U69.G2(VDD.4) U69.G8(VDD.5) U69.K1(VDD.6) U69.K9(VDD.7) U69.M1(VDD.8) U69.M9(VDD.9) U115.A2(VDD.1) U115.A9(VDD.2) U115.B9(VDDQ.1) U115.C1(VDDQ.2) U115.D7(VDD.3) U115.E2(VDDQ.3) U115.E9(VDDQ.4) U115.G2(VDD.4) U115.G8(VDD.5) U115.K1(VDD.6) U115.K9(VDD.7) U115.M1(VDD.8) U115.M9(VDD.9) U116.A2(VDD.1) U116.A9(VDD.2) U116.B9(VDDQ.1) U116.C1(VDDQ.2) U116.D7(VDD.3) U116.E2(VDDQ.3) U116.E9(VDDQ.4) U116.G2(VDD.4) U116.G8(VDD.5) U116.K1(VDD.6) U116.K9(VDD.7) U116.M1(VDD.8) U116.M9(VDD.9)
VDD_DSPEVE_IVA_GPU: C89.1 C90.2 C105.2 C107.1 C108.2 C109.1 C111.2 C112.1 C118.1 C119.1 C349.2 C372.1 C373.2 C374.2 C377.2 C453.2 C460.1 C463.1 C465.2 C466.1 C469.1 C473.1 C474.1 C475.1 C478.2 C483.2 C492.1 C495.1 L14.1 L16.1 U45.K2(SMPS45_FDBK) U52.J13(VDD_DSPEVE.7) U52.K10(VDD_DSPEVE.8) U52.K11(VDD_DSPEVE.9) U52.K12(VDD_DSPEVE.10) U52.K13(VDD_DSPEVE.11) U52.L10(VDD_DSPEVE.2) U52.L11(VDD_DSPEVE.4) U52.L12(VDD_DSPEVE.12) U52.M10(VDD_DSPEVE.1) U52.M11(VDD_DSPEVE.5) U52.M12(VDD_DSPEVE.3) U52.M13(VDD_DSPEVE.6) U52.U11(VDD_GPU.5) U52.U12(VDD_GPU.6) U52.U18(VDD_IVA.1) U52.U19(VDD_IVA.2) U52.V10(VDD_GPU.2) U52.V11(VDD_GPU.3) U52.V14(VDD_GPU.7) U52.V18(VDD_IVA.3) U52.V19(VDD_IVA.4) U52.W10(VDD_GPU.1) U52.W11(VDD_GPU.4) U52.W13(VDD_GPU.8)
VDD_MPU: C91.2 C92.2 C93.2 C94.2 C95.2 C96.2 C356.1 C359.2 C360.2 C365.1 C366.1 C367.2 C368.2 C369.1 C370.2 C378.2 C384.1 C385.1 C387.1 C389.1 C391.2 C392.2 C396.1 C410.2 L15.1 L17.1 R554.1 U45.B13(SMPS12_FBK) U52.K17(VDD_MPU.10) U52.K18(VDD_MPU.2) U52.L15(VDD_MPU.11) U52.L16(VDD_MPU.12) U52.L17(VDD_MPU.6) U52.L18(VDD_MPU.8) U52.L19(VDD_MPU.3) U52.M15(VDD_MPU.13) U52.M16(VDD_MPU.14) U52.M17(VDD_MPU.5) U52.M18(VDD_MPU.7) U52.N17(VDD_MPU.4) U52.N18(VDD_MPU.1) U52.P17(VDD_MPU.15) U52.P18(VDD_MPU.9) U52.R18(VDD_MPU.16)
VDD_RTC: C102.2 C117.1 R531.1 U45.A5(LDO9_OUT) U52.AB15(VDD_RTC)
VDDA_ANA: C680.1 U45.C8(LDOVANA_OUT)
VDDA_DEBUG_1V8: C414.2 C420.1 C427.1 C490.1 E4.1 U52.N11(VDDA_DEBUG) U52.N12(VDDA_DSP_EVE)
VDDA_HDMI: C538.1 C539.1 E9.1 U52.Y17(VDDA_HDMI)
VDDA_IVA_1V8: C415.2 C422.1 C429.1 C497.1 E3.1 U52.R14(VDDA_GPU) U52.R17(VDDA_IVA)
VDDA_MPU_1V8: C413.1 C419.1 C426.1 C507.2 E5.1 U52.M14(VDDA_ABE_PER) U52.N16(VDDA_MPU)
VDDA_PCI_1P8: C417.1 C424.1 E1.1 U52.AA16(VDDA_PCIE1) U52.AA17(VDDA_PCIE0) U52.W14(VDDA_PCIE)
VDDA_PHY_1V8: C352.1 C486.1 C510.1 C511.1 E1.3 E2.3 E9.3 U45.K11(LDO3_OUT) U52.AA13(VDDA_USB1) U52.AB12(VDDA_USB2) U52.W12(VDDA_USB3)
VDDA_PLL_1V8: C103.2 C521.1 C522.1 E3.3 E4.3 E5.3 E6.3 U45.B5(LDOLN_OUT) U52.AD16(VDDA_OSC.1) U52.AE16(VDDA_OSC.2)
VDDA_RTC: C110.1 C431.1 U45.A8(LDOVRTC_OUT) U52.AB13(VDDA_RTC)
VDDA_SATA_1P8: C416.1 C423.1 E2.1 U52.V13(VDDA_SATA)
VDDA_VIDEO_1V8: C412.2 C418.1 C425.1 C491.1 E6.1 U52.P14(VDDA_VIDEO) U52.P15(VDDA_GMAC_CORE) U52.P16(VDDA_DDR)
VDDR_VREFSTL: C147.1 C177.1 C178.1 C197.1 C198.1 C203.1 C204.1 C205.1 C514.1 C607.2 C617.1 C618.1 C619.1 C628.1 C629.1 C651.1 C652.1 U52.N22(DDR2_VREF0) U52.Y18(DDR1_VREF0) U64.6(REFOUT) U65.H1(VREFDQ) U65.M8(VREFCA) U66.H1(VREFDQ) U66.M8(VREFCA) U67.E1(VREFDQ) U67.J8(VREFCA) U68.E1(VREFDQ) U68.J8(VREFCA) U69.E1(VREFDQ) U69.J8(VREFCA) U115.E1(VREFDQ) U115.J8(VREFCA) U116.E1(VREFDQ) U116.J8(VREFCA)
VDDS_1V8: C327.2 C357.1 C371.1 C382.1 C399.2 C400.2 C401.1 C402.1 C406.1 C461.2 C470.1 C471.1 C518.2 C524.1 C530.1 E10.3 L10.1 R192.1 U45.J8(SMPS9_FBK) U52.AA7(VDDS_MLBP.1) U52.AA18(VDDS18V_DDR1.1) U52.AA19(VDDS18V_DDR1.2) U52.G18(VDDS18V.8) U52.H17(VDDS18V.11) U52.J21(VDDS18V_DDR2.3) U52.J22(VDDS18V_DDR2.4) U52.M8(VDDS18V.9) U52.M9(VDDS18V.7) U52.N8(VDDS18V.4) U52.N21(VDDS18V_DDR2.2) U52.P8(VDDS18V.5) U52.P20(VDDS18V_DDR2.5) U52.P21(VDDS18V_DDR2.1) U52.R8(VDDS18V.3) U52.T8(VDDS18V.2) U52.V21(VDDS18V.12) U52.V22(VDDS18V.6) U52.W17(VDDS18V.10) U52.W18(VDDS18V.1) U52.W21(VDDS18V_DDR1.4) U52.Y7(VDDS_MLBP.2) U52.Y21(VDDS18V_DDR1.3)
VDDSHV: C104.1 C355.1 C436.1 C437.2 C438.1 C442.1 C443.1 C444.2 C445.1 C449.1 C450.2 C454.1 C455.2 C457.1 C458.2 C464.1 C482.1 C484.1 C493.1 C494.1 C496.1 C500.1 C502.1 C526.1 C542.2 C545.1 E11.3 U52.AB6(VDDSHV7.1) U52.AB7(VDDSHV7.2) U52.AD5(VDDSHV6.2) U52.AD7(VDDSHV6.4) U52.AE7(VDDSHV6.3) U52.AF5(VDDSHV6.1) U52.B6(VDDSHV2.1) U52.B23(VDDSHV3.9) U52.C24(VDDSHV4.1) U52.D10(VDDSHV2.5) U52.D16(VDDSHV3.4) U52.D22(VDDSHV3.8) U52.E3(VDDSHV1.1) U52.E5(VDDSHV1.4) U52.E10(VDDSHV2.4) U52.E16(VDDSHV3.3) U52.E22(VDDSHV3.7) U52.G4(VDDSHV1.2) U52.G5(VDDSHV1.3) U52.G15(VDDSHV3.2) U52.H8(VDDSHV1.5) U52.H9(VDDSHV1.6) U52.H10(VDDSHV2.2) U52.H11(VDDSHV2.3) U52.H15(VDDSHV3.1) U52.H16(VDDSHV3.6) U52.H18(VDDSHV3.5) U52.H19(VDDSHV3.10) U52.J8(VDDSHV11.2) U52.K8(VDDSHV11.1) U52.N4(VDDSHV10.2) U52.N5(VDDSHV10.4) U52.P10(VDDSHV10.6) U52.R7(VDDSHV10.5) U52.R10(VDDSHV10.7) U52.T4(VDDSHV10.1) U52.T5(VDDSHV10.3) U52.U10(VDDSHV9.3) U52.W4(VDDSHV9.1) U52.W5(VDDSHV9.2)
VDDSHV5: C101.1 C485.1 C527.1 C540.1 R204.1 R530.1 R605.2 U45.B6(LDO2_OUT) U52.V12(VDDSHV5) U54.5(VIO/NC) U110.5(VCC)
VDDSHV8: C430.1 C467.1 U45.C6(LDO1_OUT) U52.W8(VDDSHV8.2) U52.Y8(VDDSHV8.1)
VIN1A_CLK0: R957.1
VIN1A_D0: RN32.4(R4A)
VIN1A_D1: RN32.3(R3A)
VIN1A_D2: RN32.2(R2A)
VIN1A_D3: RN32.1(R1A)
VIN1A_D4: RN33.4(R4A)
VIN1A_D5: RN33.3(R3A)
VIN1A_D6: RN33.2(R2A)
VIN1A_D7: RN33.1(R1A)
VIN1A_DE0: R947.1
VIN1A_FLD0: R950.1
VIN1A_HSYNC0: R948.1
VIN1A_VSYNC0: R949.1
AIC_BCLK: R253.2 R642.1 U59.38(BCLK)
AIC_DIN: R251.2 R643.1 U59.40(DIN)
AIC_DOUT: R250.2 U59.41(DOUT)
AIC_MCA3_ACLKX: R253.1
AIC_MCA3_AFSX: R252.1
AIC_MCA3_AXR0: R251.1
AIC_MCA3_AXR1: R250.1
AIC_MCLK: R254.1
AIC_WCLK: R252.2 U59.39(WCLK)
BT_EN: P9.89 U46.20(B2)
BT_UART_CTS: P9.70 U46.15(B7)
BT_UART_RTS: P9.72 U35.16(B6)
BT_UART_RX: P9.68 U46.14(B8)
BT_UART_TX: P9.66 U35.17(B5)
COMQ_MMC0_CLK: P9.20 U104.3(A)
COMQ_MMC0_CMD: P9.24 R559.2 U100.5(A4)
COMQ_MMC0_DAT0: P9.26 R560.2 U100.6(A5)
COMQ_MMC0_DAT1: P9.28 R561.2 U100.7(A6)
COMQ_MMC0_DAT2: P9.30 R562.2 U100.8(A7)
COMQ_MMC0_DAT3: P9.32 R558.2 U100.9(A8)
CON_MMC1_CLK: P14.5(CLK) R17.2 R343.2 U78.3(IO1)
CON_MMC1_CMD: P14.3(CMD) R16.2 R344.2 U78.5(IO2)
CON_MMC1_DAT0: P14.7(DAT0) R18.2 R342.2 U77.5(IO2)
CON_MMC1_DAT1: P14.8(DAT1) R19.2 R341.2 U77.3(IO1)
CON_MMC1_DAT2: P14.1(DAT2) R14.2 R340.2 U79.5(IO2)
CON_MMC1_DAT3: P14.2(DAT3) R15.2 R345.2 U79.3(IO1)
CON_USB1_DM: FL1.3 U73.6(D-)
CON_USB1_DP: FL1.2 U73.7(D+)
CON_USB2_DM: FL4.3 U72.6(D-)
CON_USB2_DP: FL4.2 U72.7(D+)
CONN_ALT_TRST_N: J17.9(NTRST) R759.2
CONN_JTAG_TRST_N: J17.8(TRSTPD) R761.1
CPU_POR_RESETN: R596.1 U62.2(A) U102.1(R\E\S\E\T)
CPU_RESETN: R623.1
DBG_RX1: R106.1
DBG_TX1: U6.1(B) U6.2(A)
DCAN1_RX: U54.4(RXD)
DCAN1_TX: R617.1 U54.1(TXD)
ENET_GPIO5_15: P1.1
ENET_GPIO5_16: P1.2
ENET_GPIO5_17: P1.4
ENET_GPIO5_20: P1.10
ENET_GPIO5_21: P1.7
ENET_GPIO5_22: P1.3
ENET_GPIO5_23: P1.6
ENET_GPIO5_24: P1.5
ENET_GPIO5_25: P1.8
ENET_GPIO5_26: P1.16
ENET_GPIO5_27: P1.13
ENET_GPIO5_28: P1.9
ENET_GPIO5_29: P1.12
ENET_GPIO5_30: P1.11
ENET_GPIO5_31: P1.14
ENET_RST_INN: R914.1 R915.1 U130.1(B)
ENET_RSTN: P1.15 U130.4(Y)
EVM_12V: D1.2(A)
FM_I2S_CLK: P9.49 U48.13(1B1)
FM_I2S_DI: P9.53 U48.11(2B1)
FM_I2S_DO: P9.51 U35.18(B4)
FM_I2S_FSYNC: P9.55 U48.12(1B2)
FTDI_RX: P1.19 R100.2
FTDI_TX: P1.21 R911.1 U129.1(B) U129.2(A)
GA1: R451.2 U23.6(GA1)
GA2: R457.2 U23.8(GA2)
GB1: R450.2 U23.33(GB1)
GB2: R456.2 U23.31(GB2)
GP5[4]: U46.4(A2)
GP5[5]: U35.5(A3)
GP5[6]: U46.6(A4)
GP5[7]: U35.3(A1)
GP5[8]: U46.5(A3)
GPMC_D00: R80.2 R110.1
GPMC_D01: R81.2 R111.1
GPMC_D02: R82.2 R112.1
GPMC_D03: J21.1 R113.2
GPMC_D04: R84.2 R114.2
GPMC_D05: J24.1 R115.2
GPMC_D06: R86.2 R116.1
GPMC_D07: R87.2 R117.1
GPMC_D08: R88.2 R118.1
GPMC_D09: R89.2 R119.1
GPMC_D10: R90.2 R120.1
GPMC_D11: R91.2 R121.1
GPMC_D12: R92.2 R122.1
GPMC_D13: R93.2 R123.1
GPMC_D14: R94.2 R124.1
GPMC_D15: R95.2 R125.1
GPS_PPS_OUT: P9.50 U35.19(B3)
GPS_TIME_STAMP: P9.48 U46.18(B4)
H_DCAN1_RX: R232.2 U52.G19(DCAN1_RX/UART8_TXD/MMC2_SDWP/SA)
H_DCAN1_TX: U52.G20(DCAN1_TX/UART8_RXD/MMC2_SDCD/HD)
H_DDR1_A0: RN4.1(R1A) TP1MA19.1 TP1MB19.1 TP1MC14.1 U52.AD20(DDR1_A0) U65.N3(A0) U66.N3(A0) U67.K3(A0)
H_DDR1_A1: RN4.2(R2A) TP1MA20.1 TP1MB20.1 TP1MC16.1 U52.AC19(DDR1_A1) U65.P7(A1) U66.P7(A1) U67.L7(A1)
H_DDR1_A2: RN6.4(R4A) TP1MA27.1 TP1MB27.1 TP1MC26.1 U52.AC20(DDR1_A2) U65.P3(A2) U66.P3(A2) U67.L3(A2)
H_DDR1_A3: RN15.4(R4A) TP1MA14.1 TP1MB14.1 TP1MC13.1 U52.AB19(DDR1_A3) U65.N2(A3) U66.N2(A3) U67.K2(A3)
H_DDR1_A4: RN4.3(R3A) TP1MA16.1 TP1MB16.1 TP1MC17.1 U52.AF21(DDR1_A4) U65.P8(A4) U66.P8(A4) U67.L8(A4)
H_DDR1_A5: RN4.4(R4A) TP1MA21.1 TP1MB21.1 TP1MC18.1 U52.AH22(DDR1_A5) U65.P2(A5) U66.P2(A5) U67.L2(A5)
H_DDR1_A6: RN17.3(R3A) TP1MA22.1 TP1MB22.1 TP1MC21.1 U52.AG23(DDR1_A6) U65.R8(A6) U66.R8(A6) U67.M8(A6)
H_DDR1_A7: RN6.2(R2A) TP1MA17.1 TP1MB17.1 TP1MC22.1 U52.AE21(DDR1_A7) U65.R2(A7) U66.R2(A7) U67.M2(A7)
H_DDR1_A8: RN17.1(R1A) TP1MA26.1 TP1MB26.1 TP1MC25.1 U52.AF22(DDR1_A8) U65.T8(A8) U66.T8(A8) U67.N8(A8)
H_DDR1_A9: RN6.1(R1A) TP1MA25.1 TP1MB25.1 TP1MC19.1 U52.AE22(DDR1_A9) U65.R3(A9) U66.R3(A9) U67.M3(A9)
H_DDR1_A10: RN13.3(R3A) TP1MA8.1 TP1MB8.1 TP1MC6.1 U52.AD21(DDR1_A10) U65.L7(A10) U66.L7(A10) U67.H7(A10/AP)
H_DDR1_A11: RN17.4(R4A) TP1MA18.1 TP1MB18.1 TP1MC20.1 U52.AD22(DDR1_A11) U65.R7(A11) U66.R7(A11) U67.M7(A11)
H_DDR1_A12: RN15.1(R1A) TP1MA13.1 TP1MB13.1 TP1MC15.1 U52.AC21(DDR1_A12) U65.N7(A12) U66.N7(A12) U67.K7(A12/B\C\)
H_DDR1_A13: RN6.3(R3A) TP1MA23.1 TP1MB23.1 TP1MC23.1 U52.AF18(DDR1_A13) U65.T3(A13) U66.T3(A13) U67.N3(A13)
H_DDR1_A14: RN17.2(R2A) TP1MA24.1 TP1MB24.1 TP1MC24.1 U52.AE17(DDR1_A14) U65.T7(A14) U66.T7(A14) U67.N7(A14/NC)
H_DDR1_A15: RN13.1(R1A) TP1MA11.1 TP1MB11.1 TP1MC9.1 U52.AD18(DDR1_A15) U65.M7(NC.M7/A15) U66.M7(NC.M7/A15) U67.J7(A15/NC)
H_DDR1_BA0: RN2.4(R4A) TP1MA9.1 TP1MB9.1 TP1MC10.1 U52.AF17(DDR1_BA0) U65.M2(BA0) U66.M2(BA0) U67.J2(BA0)
H_DDR1_BA1: RN15.3(R3A) TP1MA12.1 TP1MB12.1 TP1MC12.1 U52.AE18(DDR1_BA1) U65.N8(BA1) U66.N8(BA1) U67.K8(BA1)
H_DDR1_BA2: RN15.2(R2A) TP1MA15.1 TP1MB15.1 TP1MC11.1 U52.AB18(DDR1_BA2) U65.M3(BA2) U66.M3(BA2) U67.J3(BA2)
H_DDR1_CASN: RN2.2(R2A) TP1MA3.1 TP1MB3.1 TP1MC5.1 U52.AC18(DDR1_CASN) U65.K3(CAS#) U66.K3(CAS#) U67.G3(C\A\S\)
H_DDR1_CKE: R689.1 TP1MA2.1 TP1MB2.1 TP1MC3.1 U52.AG22(DDR1_CKE) U65.K9(CKE) U66.K9(CKE) U67.G9(CKE)
H_DDR1_CLK0: R684.1 TP1MA1.1 TP1MB1.1 TP1MC2.1 U52.AG24(DDR1_CK) U65.J7(CK) U66.J7(CK) U67.F7(CK)
H_DDR1_CLK0N: R687.1 TP1MA4.1 TP1MB4.1 TP1MC4.1 U52.AH24(DDR1_NCK) U65.K7(CK#) U66.K7(CK#) U67.G7(C\K\)
H_DDR1_CSN0: RN2.3(R3A) TP1MA10.1 TP1MB10.1 TP1MC8.1 U52.AH23(DDR1_CS0N) U65.L2(CS#) U66.L2(CS#) U67.H2(C\S\)
H_DDR1_D0: U52.AF25(DDR1_D0) U65.H7(DQ7)
H_DDR1_D1: U52.AF26(DDR1_D1) U65.F8(DQ3)
H_DDR1_D2: U52.AG26(DDR1_D2) U65.F7(DQ1)
H_DDR1_D3: U52.AH26(DDR1_D3) U65.H8(DQ5)
H_DDR1_D4: U52.AF24(DDR1_D4) U65.E3(DQ0)
H_DDR1_D5: U52.AE24(DDR1_D5) U65.H3(DQ4)
H_DDR1_D6: U52.AF23(DDR1_D6) U65.F2(DQ2)
H_DDR1_D7: U52.AE23(DDR1_D7) U65.G2(DQ6)
H_DDR1_D8: U52.AC23(DDR1_D8) U65.A2(DQ13)
H_DDR1_D9: U52.AF27(DDR1_D9) U65.B8(DQ14)
H_DDR1_D10: U52.AG27(DDR1_D10) U65.A7(DQ12)
H_DDR1_D11: U52.AF28(DDR1_D11) U65.C8(DQ10)
H_DDR1_D12: U52.AE26(DDR1_D12) U65.C3(DQ9)
H_DDR1_D13: U52.AC25(DDR1_D13) U65.D7(DQ8)
H_DDR1_D14: U52.AC24(DDR1_D14) U65.A3(DQ15)
H_DDR1_D15: U52.AD25(DDR1_D15) U65.C2(DQ11)
H_DDR1_D16: U52.V20(DDR1_D16) U66.F8(DQ3)
H_DDR1_D17: U52.W20(DDR1_D17) U66.H8(DQ5)
H_DDR1_D18: U52.AB28(DDR1_D18) U66.F7(DQ1)
H_DDR1_D19: U52.AC28(DDR1_D19) U66.F2(DQ2)
H_DDR1_D20: U52.AC27(DDR1_D20) U66.E3(DQ0)
H_DDR1_D21: U52.Y19(DDR1_D21) U66.G2(DQ6)
H_DDR1_D22: U52.AB27(DDR1_D22) U66.H7(DQ7)
H_DDR1_D23: U52.Y20(DDR1_D23) U66.H3(DQ4)
H_DDR1_D24: U52.AA23(DDR1_D24) U66.C3(DQ9)
H_DDR1_D25: U52.Y22(DDR1_D25) U66.A7(DQ12)
H_DDR1_D26: U52.Y23(DDR1_D26) U66.B8(DQ14)
H_DDR1_D27: U52.AA24(DDR1_D27) U66.A3(DQ15)
H_DDR1_D28: U52.Y24(DDR1_D28) U66.C8(DQ10)
H_DDR1_D29: U52.AA26(DDR1_D29) U66.C2(DQ11)
H_DDR1_D30: U52.AA25(DDR1_D30) U66.A2(DQ13)
H_DDR1_D31: U52.AA28(DDR1_D31) U66.D7(DQ8)
H_DDR1_DQM0: U52.AD23(DDR1_DQM0) U65.E7(LDM)
H_DDR1_DQM1: U52.AB23(DDR1_DQM1) U65.D3(UDM)
H_DDR1_DQM2: U52.AC26(DDR1_DQM2) U66.E7(LDM)
H_DDR1_DQM3: U52.AA27(DDR1_DQM3) U66.D3(UDM)
H_DDR1_DQM_ECC: U52.V26(DDR1_DQM_ECC) U67.B7(DM/TDQS)
H_DDR1_DQS0: U52.AH25(DDR1_DQS0) U65.F3(LDQS)
H_DDR1_DQS1: U52.AE27(DDR1_DQS1) U65.C7(UDQS)
H_DDR1_DQS2: U52.AD27(DDR1_DQS2) U66.F3(LDQS)
H_DDR1_DQS3: U52.Y28(DDR1_DQS3) U66.C7(UDQS)
H_DDR1_DQS_ECC: U52.V27(DDR1_DQS_ECC) U67.C3(DQS)
H_DDR1_DQSN0: U52.AG25(DDR1_DQSN0) U65.G3(LDQS#)
H_DDR1_DQSN1: U52.AE28(DDR1_DQSN1) U65.B7(UDQS#)
H_DDR1_DQSN2: U52.AD28(DDR1_DQSN2) U66.G3(LDQS#)
H_DDR1_DQSN3: U52.Y27(DDR1_DQSN3) U66.B7(UDQS#)
H_DDR1_DQSN_ECC: U52.V28(DDR1_DQSN_ECC) U67.D3(D\Q\S\)
H_DDR1_ECC_D0: U52.W22(DDR1_ECC_D0) U67.E8(DQ5)
H_DDR1_ECC_D1: U52.V23(DDR1_ECC_D1) U67.C8(DQ3)
H_DDR1_ECC_D2: U52.W19(DDR1_ECC_D2) U67.E3(DQ4)
H_DDR1_ECC_D3: U52.W23(DDR1_ECC_D3) U67.D2(DQ6)
H_DDR1_ECC_D4: U52.Y25(DDR1_ECC_D4) U67.C7(DQ1)
H_DDR1_ECC_D5: U52.V24(DDR1_ECC_D5) U67.E7(DQ7)
H_DDR1_ECC_D6: U52.V25(DDR1_ECC_D6) U67.C2(DQ2)
H_DDR1_ECC_D7: U52.Y26(DDR1_ECC_D7) U67.B3(DQ0)
H_DDR1_ODT0: RN2.1(R1A) TP1MA5.1 TP1MB5.1 TP2MC1.1 U52.AE20(DDR1_ODT0) U65.K1(ODT) U66.K1(ODT) U67.G1(ODT)
H_DDR1_RASN: RN13.4(R4A) TP1MA6.1 TP1MB6.1 TP1MC1.1 U52.AF20(DDR1_RASN) U65.J3(RAS#) U66.J3(RAS#) U67.F3(R\A\S\)
H_DDR1_RST: U52.AG21(DDR1_RST) U65.T2(RSTN) U66.T2(RSTN) U67.N2(R\E\S\E\T\)
H_DDR1_WEN: RN13.2(R2A) TP1MA7.1 TP1MB7.1 TP1MC7.1 U52.AH21(DDR1_WEN) U65.L3(WE#) U66.L3(WE#) U67.H3(W\E\)
H_DDR2_A0: RN14.1(R1A) TP2MA15.1 TP2MB15.1 U52.R25(DDR2_A0) U68.K3(A0) U69.K3(A0) U115.K3(A0) U116.K3(A0)
H_DDR2_A1: RN16.4(R4A) TP2MA19.1 TP2MB19.1 U52.R26(DDR2_A1) U68.L7(A1) U69.L7(A1) U115.L7(A1) U116.L7(A1)
H_DDR2_A2: RN5.3(R3A) TP2MA20.1 TP2MB20.1 U52.R28(DDR2_A2) U68.L3(A2) U69.L3(A2) U115.L3(A2) U116.L3(A2)
H_DDR2_A3: RN5.1(R1A) TP2MA14.1 TP2MB14.1 U52.R27(DDR2_A3) U68.K2(A3) U69.K2(A3) U115.K2(A3) U116.K2(A3)
H_DDR2_A4: RN5.4(R4A) TP2MA17.1 TP2MB17.1 U52.P23(DDR2_A4) U68.L8(A4) U69.L8(A4) U115.L8(A4) U116.L8(A4)
H_DDR2_A5: RN5.2(R2A) TP2MA18.1 TP2MB18.1 U52.P22(DDR2_A5) U68.L2(A5) U69.L2(A5) U115.L2(A5) U116.L2(A5)
H_DDR2_A6: RN7.3(R3A) TP2MA24.1 TP2MB24.1 U52.P25(DDR2_A6) U68.M8(A6) U69.M8(A6) U115.M8(A6) U116.M8(A6)
H_DDR2_A7: RN16.3(R3A) TP2MA23.1 TP2MB23.1 U52.N20(DDR2_A7) U68.M2(A7) U69.M2(A7) U115.M2(A7) U116.M2(A7)
H_DDR2_A8: RN16.1(R1A) TP2MA27.1 TP2MB27.1 U52.P27(DDR2_A8) U68.N8(A8) U69.N8(A8) U115.N8(A8) U116.N8(A8)
H_DDR2_A9: RN7.1(R1A) TP2MA21.1 TP2MB21.1 U52.N27(DDR2_A9) U68.M3(A9) U69.M3(A9) U115.M3(A9) U116.M3(A9)
H_DDR2_A10: RN3.1(R1A) TP2MA7.1 TP2MB7.1 U52.N23(DDR2_A10) U68.H7(A10/AP) U69.H7(A10/AP) U115.H7(A10/AP) U116.H7(A10/AP)
H_DDR2_A11: RN7.2(R2A) TP2MA22.1 TP2MB22.1 U52.P26(DDR2_A11) U68.M7(A11) U69.M7(A11) U115.M7(A11) U116.M7(A11)
H_DDR2_A12: RN14.3(R3A) TP2MA16.1 TP2MB16.1 U52.N28(DDR2_A12) U68.K7(A12/B\C\) U69.K7(A12/B\C\) U115.K7(A12/B\C\) U116.K7(A12/B\C\)
H_DDR2_A13: RN16.2(R2A) TP2MA26.1 TP2MB26.1 U52.T22(DDR2_A13) U68.N3(A13) U69.N3(A13) U115.N3(A13) U116.N3(A13)
H_DDR2_A14: RN7.4(R4A) TP2MA25.1 TP2MB25.1 U52.R22(DDR2_A14) U68.N7(A14/NC) U69.N7(A14/NC) U115.N7(A14/NC) U116.N7(A14/NC)
H_DDR2_A15: RN3.3(R3A) TP2MA12.1 TP2MB12.1 U52.U22(DDR2_A15) U68.J7(A15/NC) U69.J7(A15/NC) U115.J7(A15/NC) U116.J7(A15/NC)
H_DDR2_BA0: RN12.3(R3A) TP2MA10.1 TP2MB10.1 U52.U23(DDR2_BA0) U68.J2(BA0) U69.J2(BA0) U115.J2(BA0) U116.J2(BA0)
H_DDR2_BA1: RN14.2(R2A) TP2MA13.1 TP2MB13.1 U52.U27(DDR2_BA1) U68.K8(BA1) U69.K8(BA1) U115.K8(BA1) U116.K8(BA1)
H_DDR2_BA2: RN14.4(R4A) TP2MA11.1 TP2MB11.1 U52.U26(DDR2_BA2) U68.J3(BA2) U69.J3(BA2) U115.J3(BA2) U116.J3(BA2)
H_DDR2_CASN: RN12.2(R2A) TP2MA6.1 TP2MB6.1 U52.U28(DDR2_CASN) U68.G3(C\A\S\) U69.G3(C\A\S\) U115.G3(C\A\S\) U116.G3(C\A\S\)
H_DDR2_CKE: RN12.4(R4A) TP2MA1.1 TP2MB1.1 U52.U24(DDR2_CKE) U68.G9(CKE) U69.G9(CKE) U115.G9(CKE) U116.G9(CKE)
H_DDR2_CLK0: R685.1 TP2MA4.1 TP2MB4.1 U52.T28(DDR2_CK) U68.F7(CK) U69.F7(CK) U115.F7(CK) U116.F7(CK)
H_DDR2_CLK0N: R688.1 TP2MA5.1 TP2MB5.1 U52.T27(DDR2_NCK) U68.G7(C\K\) U69.G7(C\K\) U115.G7(C\K\) U116.G7(C\K\)
H_DDR2_CSN0: RN12.1(R1A) TP2MA8.1 TP2MB8.1 U52.P24(DDR2_CSN0) U68.H2(C\S\) U69.H2(C\S\) U115.H2(C\S\) U116.H2(C\S\)
H_DDR2_D0: U52.E26(DDR2_D0) U115.E7(DQ7)
H_DDR2_D1: U52.G25(DDR2_D1) U115.D2(DQ6)
H_DDR2_D2: U52.F25(DDR2_D2) U115.C8(DQ3)
H_DDR2_D3: U52.F24(DDR2_D3) U115.E8(DQ5)
H_DDR2_D4: U52.F26(DDR2_D4) U115.C7(DQ1)
H_DDR2_D5: U52.F27(DDR2_D5) U115.E3(DQ4)
H_DDR2_D6: U52.E27(DDR2_D6) U115.C2(DQ2)
H_DDR2_D7: U52.E28(DDR2_D7) U115.B3(DQ0)
H_DDR2_D8: U52.H23(DDR2_D8) U69.E3(DQ4)
H_DDR2_D9: U52.H25(DDR2_D9) U69.E7(DQ7)
H_DDR2_D10: U52.H24(DDR2_D10) U69.E8(DQ5)
H_DDR2_D11: U52.H26(DDR2_D11) U69.C7(DQ1)
H_DDR2_D12: U52.G26(DDR2_D12) U69.C8(DQ3)
H_DDR2_D13: U52.J25(DDR2_D13) U69.B3(DQ0)
H_DDR2_D14: U52.J26(DDR2_D14) U69.C2(DQ2)
H_DDR2_D15: U52.J24(DDR2_D15) U69.D2(DQ6)
H_DDR2_D16: U52.L22(DDR2_D16) U116.C7(DQ1)
H_DDR2_D17: U52.K20(DDR2_D17) U116.C2(DQ2)
H_DDR2_D18: U52.K21(DDR2_D18) U116.B3(DQ0)
H_DDR2_D19: U52.L23(DDR2_D19) U116.C8(DQ3)
H_DDR2_D20: U52.L24(DDR2_D20) U116.E8(DQ5)
H_DDR2_D21: U52.J23(DDR2_D21) U116.E7(DQ7)
H_DDR2_D22: U52.K22(DDR2_D22) U116.E3(DQ4)
H_DDR2_D23: U52.J20(DDR2_D23) U116.D2(DQ6)
H_DDR2_D24: U52.L27(DDR2_D24) U68.C7(DQ1)
H_DDR2_D25: U52.L26(DDR2_D25) U68.E8(DQ5)
H_DDR2_D26: U52.L25(DDR2_D26) U68.C8(DQ3)
H_DDR2_D27: U52.L28(DDR2_D27) U68.E3(DQ4)
H_DDR2_D28: U52.M23(DDR2_D28) U68.E7(DQ7)
H_DDR2_D29: U52.M24(DDR2_D29) U68.D2(DQ6)
H_DDR2_D30: U52.M25(DDR2_D30) U68.B3(DQ0)
H_DDR2_D31: U52.M26(DDR2_D31) U68.C2(DQ2)
H_DDR2_DQM0: U52.F28(DDR2_DQM0) U115.B7(DM/TDQS)
H_DDR2_DQM1: U52.G24(DDR2_DQM1) U69.B7(DM/TDQS)
H_DDR2_DQM2: U52.K23(DDR2_DQM2) U116.B7(DM/TDQS)
H_DDR2_DQM3: U52.M22(DDR2_DQM3) U68.B7(DM/TDQS)
H_DDR2_DQS0: U52.G28(DDR2_DQS0) U115.C3(DQS)
H_DDR2_DQS1: U52.H27(DDR2_DQS1) U69.C3(DQS)
H_DDR2_DQS2: U52.K27(DDR2_DQS2) U116.C3(DQS)
H_DDR2_DQS3: U52.M28(DDR2_DQS3) U68.C3(DQS)
H_DDR2_DQSN0: U52.G27(DDR2_DQSN0) U115.D3(D\Q\S\)
H_DDR2_DQSN1: U52.H28(DDR2_DQSN1) U69.D3(D\Q\S\)
H_DDR2_DQSN2: U52.K28(DDR2_DQSN2) U116.D3(D\Q\S\)
H_DDR2_DQSN3: U52.M27(DDR2_DQSN3) U68.D3(D\Q\S\)
H_DDR2_ODT0: RN3.2(R2A) TP2MA3.1 TP2MB3.1 U52.R23(DDR2_ODT0) U68.G1(ODT) U69.G1(ODT) U115.G1(ODT) U116.G1(ODT)
H_DDR2_RASN: R286.1 TP2MA2.1 TP2MB2.1 U52.T23(DDR2_RASN) U68.F3(R\A\S\) U69.F3(R\A\S\) U115.F3(R\A\S\) U116.F3(R\A\S\)
H_DDR2_RST: U52.R24(DDR2_RST) U68.N2(R\E\S\E\T\) U69.N2(R\E\S\E\T\) U115.N2(R\E\S\E\T\) U116.N2(R\E\S\E\T\)
H_DDR2_WEN: RN3.4(R4A) TP2MA9.1 TP2MB9.1 U52.U25(DDR2_WEN) U68.H3(W\E\) U69.H3(W\E\) U115.H3(W\E\) U116.H3(W\E\)
H_EMU0: R627.2 U52.G21(EMU0)
H_EMU0_S1: J17.19(TRD0.1) R627.1 R828.2
H_EMU1: R653.2 U52.D24(EMU1)
H_EMU1_S1: J17.21(TRD0.2) R653.1 R829.2
H_GPIO1_15_WAKEUP_CAN: R232.1
H_GPIO5_18: U52.V2(UART3_RXD/RMII1_CRS/MII0_RXDV/V)
H_GPIO5_19: U52.Y1(UART3_TXD/RMII1_RXER/MII0_RXCLK)
H_GPIO6_10: U52.AC5(GPIO6_10/MDIO_MCLK/I2C3_SDA/USB)
H_GPIO6_11: U52.AB4(GPIO6_11/MDIO_D/I2C3_SCL/USB3_U)
H_GPIO6_16: U52.F21(GPIO6_16/MCASP1_AXR10/VOUT2_FLD)
H_GPIO6_28: U52.Y9(MMC1_SDWP/UART6_TXD/I2C4_SCL/GP)
H_GPIO7_7: U52.A25(SPI1_SCLK/GPIO7_7)
H_GPIO7_8: U52.F16(SPI1_D1/GPIO7_8)
H_GPIO7_9: U52.B25(SPI1_D0/GPIO7_9)
H_GPIO7_10: U52.A24(SPI1_CS0/GPIO7_10)
H_GPIO7_11: U52.A22(SPI1_CS1/SATA1_LED/SPI2_CS1/GPI)
H_GPMC_A0: U52.R6(GPMC_A0/VIN3A_D16/VOUT3_D16/VIN)
H_GPMC_A1: U52.T9(GPMC_A1/VIN3A_D17/VOUT3_D17/VIN)
H_GPMC_A2: U52.T6(GPMC_A2/VIN3A_D18/VOUT3_D18/VIN)
H_GPMC_A3: U52.T7(GPMC_A3/QSPI1_CS2/VIN3A_D19/VOU)
H_GPMC_A4: U52.P6(GPMC_A4/QSPI1_CS3/VIN3A_D20/VOU)
H_GPMC_A5: U52.R9(GPMC_A5/VIN3A_D21/VOUT3_D21/VIN)
H_GPMC_A6: U52.R5(GPMC_A6/VIN3A_D22/VOUT3_D22/VIN)
H_GPMC_A7: U52.P5(GPMC_A7/VIN3A_D23/VOUT3_D23/VIN)
H_GPMC_A8: U52.N7(GPMC_A8/VIN3A_HSYNC0/VOUT3_HSYN)
H_GPMC_A9: U52.R4(GPMC_A9/VIN3A_VSYNC0/VOUT3_VSYN)
H_GPMC_A10: U52.N9(GPMC_A10/VIN3A_DE0/VOUT3_DE/VIN)
H_GPMC_A11: U52.P9(GPMC_A11/VIN3A_FLD0/VOUT3_FLD/V)
H_GPMC_A12: U52.P4(GPMC_A12/VIN4A_CLK0/GPMC_A0/VIN)
H_GPMC_ADV_N: U52.N1(GPMC_ADVN_ALE/GPMC_CS6/CLKOUT2/)
H_GPMC_BEN0: U52.N6(GPMC_BEN0/GPMC_CS4/VIN1B_HSYNC1)
H_GPMC_BEN1: U52.M4(GPMC_BEN1/GPMC_CS5/VIN1B_DE1/VI)
H_GPMC_CLK: R494.2 U52.P7(GPMC_CLK/GPMC_CS7/CLKOUT1/GPMC_)
H_GPMC_CLK_S1: R494.1
H_GPMC_CS0_N: U52.T1(GPMC_CS0/GPIO2_19)
H_GPMC_CS1_N: U52.H6(GPMC_CS1/MMC2_CMD/GPMC_A22/VIN4)
H_GPMC_CS2_N: U52.P2(GPMC_CS2/QSPI1_CS0/GPIO2_20)
H_GPMC_CS3_N: U52.P1(GPMC_CS3/QSPI1_CS1/VIN3A_CLK0/V)
H_GPMC_D00: U52.M6(GPMC_AD0/VIN3A_D0/VOUT3_D0/GPIO)
H_GPMC_D01: U52.M2(GPMC_AD1/VIN3A_D1/VOUT3_D1/GPIO)
H_GPMC_D02: U52.L5(GPMC_AD2/VIN3A_D2/VOUT3_D2/GPIO)
H_GPMC_D03: U52.M1(GPMC_AD3/VIN3A_D3/VOUT3_D3/GPIO)
H_GPMC_D04: U52.L6(GPMC_AD4/VIN3A_D4/VOUT3_D4/GPIO)
H_GPMC_D05: U52.L4(GPMC_AD5/VIN3A_D5/VOUT3_D5/GPIO)
H_GPMC_D06: U52.L3(GPMC_AD6/VIN3A_D6/VOUT3_D6/GPIO)
H_GPMC_D07: U52.L2(GPMC_AD7/VIN3A_D7/VOUT3_D7/GPIO)
H_GPMC_D08: U52.L1(GPMC_AD8/VIN3A_D8/VOUT3_D8/GPIO)
H_GPMC_D09: U52.K2(GPMC_AD9/VIN3A_D9/VOUT3_D9/GPIO)
H_GPMC_D10: U52.J1(GPMC_AD10/VIN3A_D10/VOUT3_D10/G)
H_GPMC_D11: U52.J2(GPMC_AD11/VIN3A_D11/VOUT3_D11/G)
H_GPMC_D12: U52.H1(GPMC_AD12/VIN3A_D12/VOUT3_D12/G)
H_GPMC_D13: U52.J3(GPMC_AD13/VIN3A_D13/VOUT3_D13/G)
H_GPMC_D14: U52.H2(GPMC_AD14/VIN3A_D14/VOUT3_D14/G)
H_GPMC_D15: U52.H3(GPMC_AD15/VIN3A_D15/VOUT3_D15/G)
H_GPMC_OE_N: U52.M5(GPMC_OEN_REN/GPIO2_24)
H_GPMC_WAIT0: U52.N2(GPMC_WAIT0/GPIO2_28)
H_GPMC_WE_N: U52.M3(GPMC_WEN/GPIO2_25)
H_HDMI_TX0+: TP98.1(TP) U52.AH17(HDMI1_DATA0Y)
H_HDMI_TX0-: TP97.1(TP) U52.AG17(HDMI1_DATA0X)
H_HDMI_TX1+: TP99.1(TP) U52.AH18(HDMI1_DATA1Y)
H_HDMI_TX1-: TP100.1(TP) U52.AG18(HDMI1_DATA1X)
H_HDMI_TX2+: TP101.1(TP) U52.AH19(HDMI1_DATA2Y)
H_HDMI_TX2-: TP102.1(TP) U52.AG19(HDMI1_DATA2X)
H_HDMI_TXC+: TP103.1(TP) U52.AH16(HDMI1_CLOCKY)
H_HDMI_TXC-: TP104.1(TP) U52.AG16(HDMI1_CLOCKX)
H_I2C1_SCL: R618.2 R624.2 U52.C20(I2C1_SCL) U52.C21(I2C1_SDA)
H_I2C2_SCL: R633.2 R652.2 U52.C25(I2C2_SDA/HDMI1_DDC_SCL) U52.F17(I2C2_SCL/HDMI1_DDC_SDA)
H_I2C3_SCL: R866.1 U52.F20(GPIO6_15/MCASP1_AXR9/DCAN2_RX/U)
H_I2C3_SDA: R867.1 U52.E21(GPIO6_14/MCASP1_AXR8/DCAN2_TX/U)
H_JTAG_RTCK: R635.2 U52.E18(RTCK)
H_JTAG_RTCK_S1: J17.7(RTCK) R635.1
H_JTAG_TCK: J17.3(TCK) U52.E20(TCLK)
H_JTAG_TDI: J17.5(TDI) U52.D23(TDI)
H_JTAG_TDO: R634.2 U52.F19(TDO)
H_JTAG_TDO_S1: J17.4(TDO) R634.1
H_JTAG_TMS: J17.2(TMS) U52.F18(TMS)
H_JTAG_TRST_N: R760.2 R761.2 U52.D20(TRSTN)
H_LJCB_CLKN: U52.AH15(LJCB_CLKN)
H_MCASP1_ACLKR: U52.B14(MCASP1_ACLKR/MCASP7_AXR2/VOUT2_)
H_MCASP1_ACLKX: U52.C14(MCASP1_ACLKX/VIN6A_FLD0/I2C3_SD)
H_MCASP1_AXR0: U52.G12(MCASP1_AXR0/UART6_RXD/VIN6A_VSY)
H_MCASP1_AXR1: U52.F12(MCASP1_AXR1/UART6_TXD/VIN6A_HSY)
H_MCASP1_AXR2: U52.G13(MCASP1_AXR2/MCASP6_AXR2/UART6_C)
H_MCASP1_AXR3: U52.J11(MCASP1_AXR3/MCASP6_AXR3/UART6_R)
H_MCASP1_AXR4: U52.E12(MCASP1_AXR4/MCASP4_AXR2/VOUT2_D)
H_MCASP1_AXR5: U52.F13(MCASP1_AXR5/MCASP4_AXR3/VOUT2_D)
H_MCASP1_AXR6: U52.C12(MCASP1_AXR6/MCASP5_AXR2/VOUT2_D)
H_MCASP1_AXR7: U52.D12(MCASP1_AXR7/MCASP5_AXR3/VOUT2_D)
H_MCASP1_AXR8: U52.B12(MCASP1_AXR8/MCASP6_AXR0/SPI3_SC)
H_MCASP1_AXR9: U52.A11(MCASP1_AXR9/MCASP6_AXR1/SPI3_D1)
H_MCASP1_AXR10: U52.B13(MCASP1_AXR10/MCASP6_ACLKX/MCASP)
H_MCASP1_AXR11: U52.A12(MCASP1_AXR11/MCASP6_FSX/MCASP6_)
H_MCASP1_AXR12: U52.E14(MCASP1_AXR12/MCASP7_AXR0/SPI3_C)
H_MCASP1_AXR13: U52.A13(MCASP1_AXR13/MCASP7_AXR1/VIN6A_)
H_MCASP1_AXR14: U52.G14(MCASP1_AXR14/MCASP7_ACLKX/MCASP)
H_MCASP1_AXR15: U52.F14(MCASP1_AXR15/MCASP7_FSX/MCASP7_)
H_MCASP1_FSR: U52.J14(MCASP1_FSR/MCASP7_AXR3/VOUT2_D1)
H_MCASP1_FSX: U52.D14(MCASP1_FSX/VIN6A_DE0/I2C3_SCL/G)
H_MCASP2_ACLKR: U52.E15(MCASP2_ACLKR/MCASP8_AXR2/VOUT2_)
H_MCASP2_ACLKX: U52.A19(MCASP2_ACLKX/VIN6A_D7)
H_MCASP2_AXR0: U52.B15(MCASP2_AXR0/VOUT2_D10/VIN4A_D10)
H_MCASP2_AXR1: U52.A15(MCASP2_AXR1/VOUT2_D11/VIN4A_D11)
H_MCASP2_AXR2: U52.C15(MCASP2_AXR2/MCASP3_AXR2/VIN6A_D)
H_MCASP2_AXR3: U52.A16(MCASP2_AXR3/MCASP3_AXR3/VIN6A_D)
H_MCASP2_AXR4: U52.D15(MCASP2_AXR4/MCASP8_AXR0/VOUT2_D)
H_MCASP2_AXR5: U52.B16(MCASP2_AXR5/MCASP8_AXR1/VOUT2_D)
H_MCASP2_AXR6: U52.B17(MCASP2_AXR6/MCASP8_ACLKX/MCASP8)
H_MCASP2_AXR7: U52.A17(MCASP2_AXR7/MCASP8_FSX/MCASP8_F)
H_MCASP2_FSR: U52.A20(MCASP2_FSR/MCASP8_AXR3/VOUT2_D9)
H_MCASP2_FSX: U52.A18(MCASP2_FSX/VIN6A_D6)
H_MCASP3_ACLKX: U52.B18(MCASP3_ACLKX/MCASP3_ACLKR/MCASP)
H_MCASP3_AFSX: U52.F15(MCASP3_FSX/MCASP3_FSR/MCASP2_AX)
H_MCASP3_AXR0: U52.B19(MCASP3_AXR0/MCASP2_AXR14/UART7_)
H_MCASP3_AXR1: U52.C17(MCASP3_AXR1/MCASP2_AXR15/UART7_)
H_MCASP4_ACLKX: U52.C18(MCASP4_ACLKX/MCASP4_ACLKR/SPI3_)
H_MCASP4_AFSX: U52.A21(MCASP4_FSX/MCASP4_FSR/SPI3_D1/U)
H_MCASP4_AXR0: U52.G16(MCASP4_AXR0/SPI3_D0/UART8_CTSN/)
H_MCASP4_AXR1: U52.D17(MCASP4_AXR1/SPI3_CS0/UART8_RTSN)
H_MCASP5_ACLKX: U52.AA3(MCASP5_ACLKX/MCASP5_ACLKR/SPI4_)
H_MCASP5_AFSX: U52.AB9(MCASP5_FSX/MCASP5_FSR/SPI4_D1/U)
H_MCASP5_AXR0: U52.AB3(MCASP5_AXR0/SPI4_D0/UART9_CTSN/)
H_MCASP5_AXR1: U52.AA4(MCASP5_AXR1/SPI4_CS0/UART9_RTSN)
H_MDIO_D: R931.2 U52.U4(MDIO_D/UART3_CTSN/MII0_TXER/VIN)
H_MDIO_D_S1: R931.1
H_MDIO_MCLK: R930.2 U52.V1(MDIO_MCLK/UART3_RTSN/MII0_COL/V)
H_MDIO_MCLK_S1: R930.1
H_MLBP_CLK_N: R184.2 TP106.1(TP) U52.AB2(MLBP_CLK_N)
H_MLBP_CLK_P: R184.1 TP105.1(TP) U52.AB1(MLBP_CLK_P)
H_MLBP_DAT_N: R183.2 TP108.1(TP) U52.AA2(MLBP_DAT_N)
H_MLBP_DAT_P: R183.1 TP107.1(TP) U52.AA1(MLBP_DAT_P)
H_MLBP_SIG_N: R182.2 TP110.1(TP) U52.AC2(MLBP_SIG_N)
H_MLBP_SIG_P: R182.1 TP109.1(TP) U52.AC1(MLBP_SIG_P)
H_MMC1_CLK: R343.1 U52.W6(MMC1_CLK/GPIO6_21)
H_MMC1_CMD: R344.1 U52.Y6(MMC1_CMD/GPIO6_22)
H_MMC1_DAT0: R342.1 U52.AA6(MMC1_DAT0/GPIO6_23)
H_MMC1_DAT1: R341.1 U52.Y4(MMC1_DAT1/GPIO6_24)
H_MMC1_DAT2: R340.1 U52.AA5(MMC1_DAT2/GPIO6_25)
H_MMC1_DAT3: R345.1 U52.Y3(MMC1_DAT3/GPIO6_26)
H_MMC1_SD_CD: P14.9(INSERT) R327.2 U52.W7(MMC1_SDCD/UART6_RXD/I2C4_SDA/GP) U131.5(IO2)
H_MMC2_CLK: R495.2 U52.J7(GPMC_A23/MMC2_CLK/GPMC_A17/VIN4)
H_MMC2_CLK_S1: R495.1
H_MMC2_DAT0: RN31.5(R4B) U52.J4(GPMC_A24/MMC2_DAT0/GPMC_A18/VIN)
H_MMC2_DAT0_S1: RN31.4(R4A)
H_MMC2_DAT1: RN31.6(R3B) U52.J6(GPMC_A25/MMC2_DAT1/GPMC_A19/VIN)
H_MMC2_DAT1_S1: RN31.3(R3A)
H_MMC2_DAT2: RN31.7(R2B) U52.H4(GPMC_A26/MMC2_DAT2/GPMC_A20/VIN)
H_MMC2_DAT2_S1: RN31.2(R2A)
H_MMC2_DAT3: RN31.8(R1B) U52.H5(GPMC_A27/MMC2_DAT3/GPMC_A21/VIN)
H_MMC2_DAT3_S1: RN31.1(R1A)
H_MMC2_DAT4: RN30.5(R4B) U52.K7(GPMC_A19/MMC2_DAT4/GPMC_A13/VIN)
